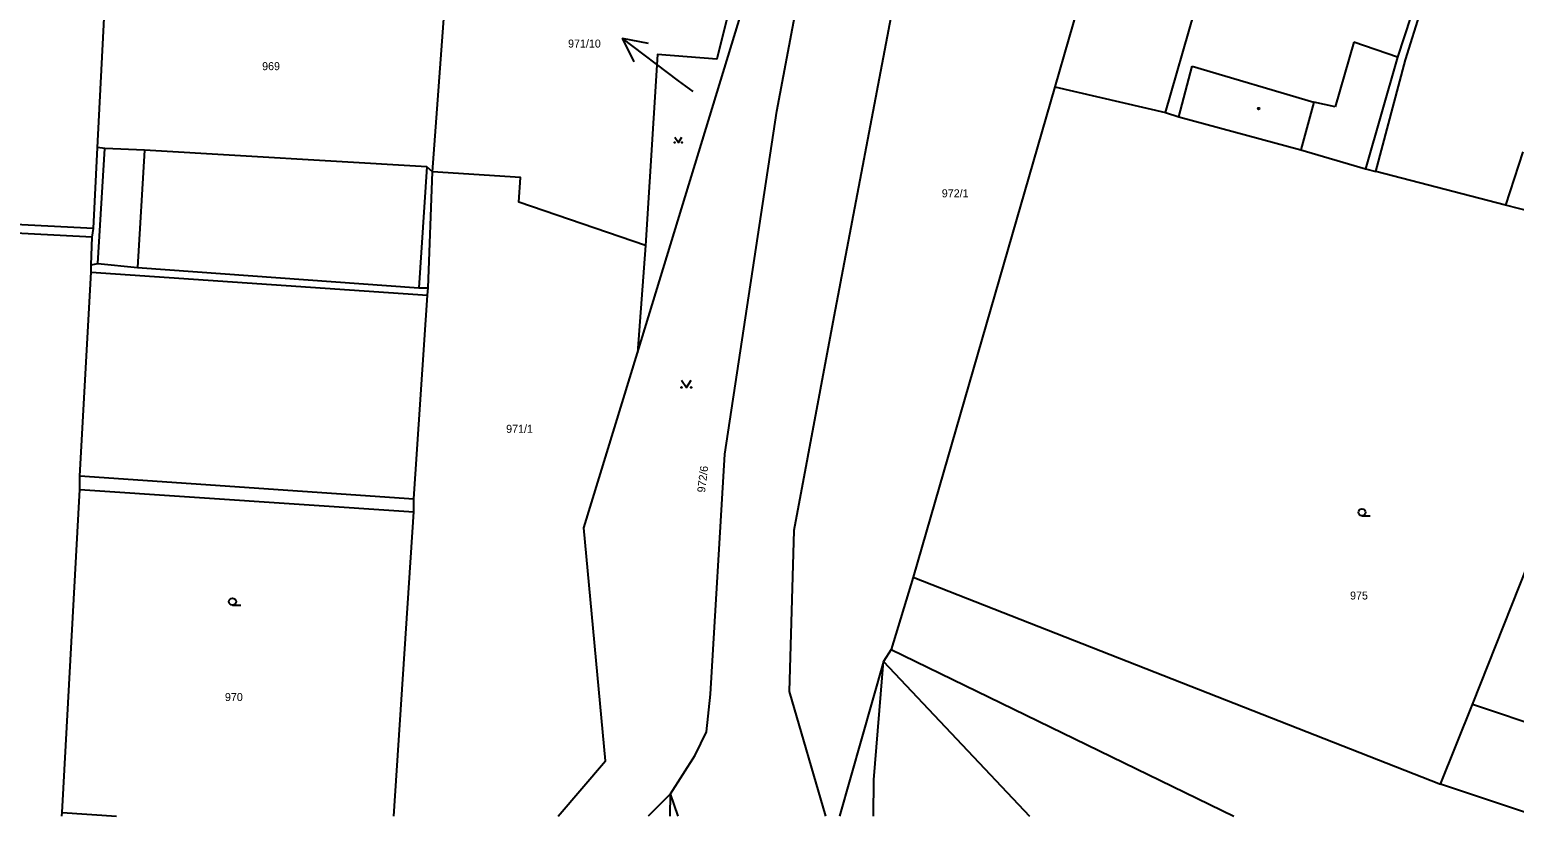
# Model space of a CAD drawing. Extents: x -599717 to -599336, y -1161826 to -1161587.
# Drawn here: x -599494.8 to -599431.7, y -1161826.1 to -1161792.7 of the extents above; entities that cross this region are included whole.
import ezdxf

# ---------------------------------------------------------------- set-up
doc = ezdxf.new("R2010")
doc.units = 0
for name, color, linetype in [('KN_Hranice parcel', 7, 'Continuous'), ('KN_Parcelní čísla', 7, 'Continuous'), ('KN_Pop  PČ popisy', 7, 'Continuous'), ('KN_Vnitřní kresba', 7, 'Continuous'), ('KN_Značky budov', 7, 'Continuous'), ('KN_Značky kultur', 7, 'Continuous')]:
    doc.layers.add(name, color=color, linetype=linetype)

msp = doc.modelspace()

# ---------------------------------------------------------------- linework, layer by layer
at = {"layer": 'KN_Hranice parcel'}
for p, q in [((-599477.69, -1161798.74), (-599476.77, -1161786.51)), ((-599468.98, -1161806.42), (-599462.84, -1161786.37)), ((-599492.14, -1161801.51), (-599505.78, -1161800.82)), ((-599468.64, -1161801.87), (-599468.98, -1161806.42)), ((-599492.19, -1161803), (-599477.89, -1161803.98)), ((-599458.2, -1161819.02), (-599458.52, -1161819.53)), ((-599458.2, -1161819.02), (-599443.639, -1161826.104)), ((-599458.52, -1161819.53), (-599452.321, -1161826.104)), ((-599467.57, -1161825.15), (-599466.52, -1161823.51)), ((-599467.57, -1161825.15), (-599468.516, -1161826.104)), ((-599467.584, -1161826.104), (-599467.57, -1161825.15)), ((-599467.243, -1161826.104), (-599467.57, -1161825.15))]:
    msp.add_line(p, q, dxfattribs=at)
for points in [[(-599447.27, -1161767.4), (-599452.95, -1161787.97), (-599450.08, -1161791.1), (-599451.24, -1161795.13)], [(-599466.52, -1161823.51), (-599466.05, -1161822.52), (-599465.87, -1161820.92), (-599465.26, -1161810.73), (-599463.06, -1161796.16), (-599462.25, -1161791.88), (-599459.44, -1161781.45)], [(-599418.94, -1161784.98), (-599424.46, -1161802.1), (-599429.9, -1161800.72), (-599432.1, -1161800.15), (-599437.61, -1161798.73)], [(-599492.14, -1161801.51), (-599492.09, -1161801.14), (-599491.92, -1161797.71), (-599491.29, -1161785.62)], [(-599463.67, -1161786.17), (-599465.6, -1161793.95), (-599468.13, -1161793.76), (-599468.64, -1161801.87)], [(-599437.61, -1161798.73), (-599436.35, -1161793.98), (-599435.02, -1161789.72)], [(-599451.24, -1161795.13), (-599457.27, -1161815.95), (-599458.2, -1161819.02)], [(-599451.24, -1161795.13), (-599446.55, -1161796.22), (-599445.98, -1161796.4), (-599440.8, -1161797.8), (-599438.05, -1161798.61), (-599437.61, -1161798.73)], [(-599477.89, -1161803.98), (-599477.87, -1161803.67), (-599477.69, -1161798.74)], [(-599468.64, -1161801.87), (-599474.02, -1161800.03), (-599473.95, -1161798.98), (-599477.69, -1161798.74)], [(-599492.19, -1161803), (-599492.18, -1161802.69), (-599492.14, -1161801.51)], [(-599493.424, -1161826.104), (-599493.42, -1161825.94), (-599492.67, -1161812.23), (-599492.66, -1161811.65), (-599492.19, -1161803)], [(-599479.325, -1161826.104), (-599478.47, -1161813.18), (-599478.48, -1161812.62), (-599477.89, -1161803.98)], [(-599472.34, -1161826.104), (-599470.33, -1161823.75), (-599471.26, -1161813.86), (-599468.98, -1161806.42)], [(-599430.792, -1161826.104), (-599434.86, -1161824.74), (-599433.51, -1161821.35), (-599430.51, -1161813.83), (-599426.51, -1161815.23), (-599424.47, -1161815.86), (-599424.04, -1161816.09)], [(-599458.52, -1161819.53), (-599460.396, -1161826.104)], [(-599458.956, -1161826.104), (-599458.93, -1161824.55), (-599458.52, -1161819.53)]]:
    msp.add_lwpolyline(points, dxfattribs=at)
at = {"layer": 'KN_Pop  PČ popisy'}
for p, q in [((-599467.23, -1161794.87), (-599469.627, -1161793.064)), ((-599469.627, -1161793.064), (-599468.526, -1161793.267)), ((-599469.627, -1161793.064), (-599469.128, -1161794.067)), ((-599466.61, -1161795.33), (-599467.23, -1161794.87))]:
    msp.add_line(p, q, dxfattribs=at)
at = {"layer": 'KN_Vnitřní kresba'}
for p, q in [((-599457.21, -1161786.88), (-599460.63, -1161804.9)), ((-599435.31, -1161789.63), (-599436.69, -1161793.87)), ((-599446.55, -1161796.22), (-599445.31, -1161791.94)), ((-599438.55, -1161793.23), (-599439.34, -1161795.98)), ((-599436.69, -1161793.87), (-599438.55, -1161793.23)), ((-599445.98, -1161796.4), (-599445.41, -1161794.25)), ((-599445.41, -1161794.25), (-599440.24, -1161795.78)), ((-599436.69, -1161793.87), (-599438.05, -1161798.61)), ((-599440.24, -1161795.78), (-599440.8, -1161797.8)), ((-599439.34, -1161795.98), (-599440.24, -1161795.78)), ((-599491.61, -1161797.75), (-599491.92, -1161797.71)), ((-599491.9, -1161802.63), (-599491.61, -1161797.75)), ((-599489.92, -1161797.82), (-599491.61, -1161797.75)), ((-599489.92, -1161797.82), (-599490.21, -1161802.8)), ((-599477.93, -1161798.53), (-599489.92, -1161797.82)), ((-599431.36, -1161797.89), (-599432.1, -1161800.15)), ((-599477.93, -1161798.53), (-599478.26, -1161803.66)), ((-599477.69, -1161798.74), (-599477.93, -1161798.53)), ((-599492.09, -1161801.14), (-599495.97, -1161800.94)), ((-599492.18, -1161802.69), (-599491.9, -1161802.63)), ((-599491.9, -1161802.63), (-599490.21, -1161802.8)), ((-599490.21, -1161802.8), (-599478.26, -1161803.66)), ((-599478.26, -1161803.66), (-599477.87, -1161803.67)), ((-599460.63, -1161804.9), (-599462.34, -1161813.97)), ((-599492.66, -1161811.65), (-599478.48, -1161812.62)), ((-599492.67, -1161812.23), (-599478.47, -1161813.18)), ((-599462.34, -1161813.97), (-599462.53, -1161820.81)), ((-599457.27, -1161815.95), (-599434.86, -1161824.74)), ((-599462.53, -1161820.81), (-599460.991, -1161826.104)), ((-599429.43, -1161822.73), (-599433.51, -1161821.35)), ((-599493.42, -1161825.94), (-599491.112, -1161826.104))]:
    msp.add_line(p, q, dxfattribs=at)
at = {"layer": 'KN_Značky budov'}
msp.add_circle((-599442.591, -1161796.05), 0.035, dxfattribs=at)
at = {"layer": 'KN_Značky kultur'}
for p, q in [((-599438.199, -1161813.35), (-599437.849, -1161813.35)), ((-599486.179, -1161817.14), (-599485.829, -1161817.14))]:
    msp.add_line(p, q, dxfattribs=at)
for points in [[(-599467.394, -1161797.259), (-599467.24, -1161797.49), (-599467.086, -1161797.259)], [(-599467.1, -1161807.59), (-599466.9, -1161807.89), (-599466.7, -1161807.59)]]:
    msp.add_lwpolyline(points, dxfattribs=at)
for centre, radius in [((-599467.394, -1161797.49), 0.0154), ((-599467.086, -1161797.49), 0.0154), ((-599467.1, -1161807.89), 0.02), ((-599466.7, -1161807.89), 0.02), ((-599438.199, -1161813.2), 0.15), ((-599486.179, -1161816.99), 0.15)]:
    msp.add_circle(centre, radius, dxfattribs=at)

# ---------------------------------------------------------------- texts
at = {"layer": 'KN_Parcelní čísla'}
for s, p in [('971/10', (-599471.925, -1161793.46)), ('969', (-599484.921, -1161794.42)), ('972/1', (-599456.048, -1161799.82)), ('971/1', (-599474.555, -1161809.82)), ('975', (-599438.705, -1161816.9)), ('970', (-599486.501, -1161821.21))]:
    msp.add_text(s, height=0.34, dxfattribs=at).set_placement(p)
msp.add_text('972/6', height=0.34, rotation=83, dxfattribs=at).set_placement((-599466.106, -1161812.373))

doc.saveas('drawing.dxf')
